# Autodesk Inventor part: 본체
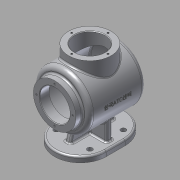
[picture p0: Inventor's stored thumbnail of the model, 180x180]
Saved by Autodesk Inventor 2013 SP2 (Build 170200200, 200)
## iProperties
Created: 2023-01
Part Number: 본체
Material: 알루미늄 6061
Document SubType Name: Modeling
Designer: aa
Density: 2.71 g/cm^3
Mass: 1038.32 g
Surface Area: 1157.53 cm^2
Volume: 383.145 cm^3
Author: aa
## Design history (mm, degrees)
sketch "스케치1"
  geometry: L1 (-63, 0)-(59, 0); L2 (-63, 0)-(-63, 38); L3 (-63, 38)-(-51, 38); L4 (-51, 38)-(-51, 50); L5 (-51, 50)-(48.087, 50); L6 (-63, 27)-(-46, 27); L7 (-46, 27)-(-46, 45); L8 (-46, 45)-(44.83, 45); A1 r 120 centre (-61, 0) between (59, 0) and (48.087, 50); A2 r 115 centre (-61, 0) between (54, 0) and (44.83, 45); 2 further points
  constraints: 16 end point, 4 parallel, 4 point on circle, 3 perpendicular, 3 point on line, 2 centre point, 1 coincident, 1 horizontal, 1 horizontal alignment, 1 midpoint
  dimensions: "d0" = 122 distance of L1.start L1.end; "d1" = 120 radius of A1; "d2" = 76 diameter of L3 L1; "d3" = 100 diameter of L5 L1; "d4" = 12 distance of L2.end L3.end; "d5" = 5 radial gap between concentric circles of A1 A2; "d6" = 54 diameter of L6 L1; "d7" = 90 diameter of L8 L1; "d8" = 17 distance of L6.start L6.end; "d57" = 59 distance of L1.end point (0, 0)
revolve "회전1" sketch "스케치1" stored, may be unused: angle "d9" = 90 deg
fillet "모깎기1" dims "d10" = 8
fillet "모깎기2" dims "d11" = 3
fillet "모깎기3" dims "d12" = 3
chamfer "모따기1" distance "d13" = 1; stored, may be unused: second distance "d14" = 2, angle "d15" = 45 deg
sketch "스케치2"
  geometry: C1 r 38 at (0, 0) reference; 1 further point
  constraints: 1 vertical alignment
  dimensions: "d16" = 32.5 distance of C1.centre point (0, 32.5)
hole "구멍1" sketch "스케치2" at (0, 32.5) diameter "d17" = 3.242; stored, may be unused: countersink angle "d21" = 90 deg, drill point angle "d23" = 118 deg; dims "d18" = 8, "d19" = 4, "d20" = 2, "d22" = 10
fillet "모깎기4" dims "d27" = 3
node "작업 평면1"
sketch "스케치3"
  geometry: L1 (51, 42)-(51, -42) reference; C1 r 38 at (0, 0); 1 further point
  constraints: 1 centre point, 1 coincident
  dimensions: "d29" = 76 diameter of C1; "d30" = 51 distance from line of C1.centre L1
extrude "돌출1" join sketch "스케치3" stored distance "d31" = 10; taper "d32" = 0 deg
sketch "스케치4"
  geometry: C1 r 38 at (0, 0) reference; C2 r 27 at (0, 0); 1 further point
  constraints: 1 centre point, 1 coincident
  dimensions: "d33" = 54 diameter of C2
extrude "돌출2" cut sketch "스케치4" stored distance "d34" = 10; taper "d35" = 0 deg
chamfer "모따기2" distance "d36" = 1; stored, may be unused: second distance "d37" = 2, angle "d38" = 45 deg
sketch "스케치5"
  geometry: C1 r 38 at (0, 0) reference; 2 further points
  constraints: 1 vertical alignment
  dimensions: "d39" = 32.5 distance of C1.centre point (0, 32.5)
hole "구멍2" sketch "스케치5" at (0, 32.5) diameter "d40" = 3.242; stored, may be unused: countersink angle "d44" = 90 deg, drill point angle "d46" = 118 deg; dims "d41" = 8, "d42" = 4, "d43" = 2, "d45" = 10
fillet "모깎기5" dims "d50" = 3
node "작업 평면2"
sketch "스케치6"
  geometry: L1 (63, 38)-(63, -38) reference; L2 (17, -46)-(-17, -46); L3 (17, 46)-(-17, 46); A1 r 46 centre (17, 0) between (17, -46) and (17, 46); A2 r 46 centre (-17, 0) between (-17, 46) and (-17, -46); 1 further point
  constraints: 5 tangent, 4 end point, 4 point on circle, 2 centre point, 2 horizontal alignment
  dimensions: "d52" = 92 diameter of A1; "d53" = 92 diameter of A2; "d54" = 126 dimension on A2 A1
extrude "돌출3" join sketch "스케치6" distance "d55" = 10; taper "d56" = 0 deg
sketch "스케치7"
  geometry: 2 further points
  dimensions: "d58" = 30 horizontal distance of point (0, 0) point (-30, 30); "d59" = 30 horizontal distance of point (0, 0) point (-30, 30)
hole "구멍3" sketch "스케치7" at (-30, 30) diameter "d60" = 9; stored, may be unused: countersink angle "d64" = 90 deg, drill point angle "d66" = 118 deg; dims "d61" = 8, "d62" = 4, "d63" = 2, "d65" = 10
fillet "모깎기6" dims "d73" = 3
sketch "스케치8"
  geometry: L1 (-5, -35)-(5, -35); L2 (5, -35)-(5, 35); L3 (5, 35)-(-5, 35); L4 (-5, 35)-(-5, -35); L5 (-5, -35)-(5, 35); L6 (5, -35)-(-5, 35); 1 further point
  constraints: 12 end point, 2 midpoint, 2 parallel, 1 horizontal, 1 perpendicular
  dimensions: "d74" = 10 distance of L3.end L2.end; "d75" = 70 distance of L2.end L1.end
extrude "돌출4" join sketch "스케치8" stored distance "d76" = 10; taper "d77" = 0 deg
sketch "스케치9"
  geometry: L1 (-62, 27)-(-63, 28) reference; L2 (-63, 28)-(-63, 30.879) reference; L3 (-63, 30.879)-(-53, 30.879) reference; L4 (-53, 30.879)-(-52.026, 32.5) reference; L5 (-52.026, 32.5)-(-53, 34.121) reference; L6 (-53, 34.121)-(-63, 34.121) reference; L7 (-63, 34.121)-(-63, 38) reference; L8 (-63, 38)-(-54, 38) reference; L9 (-51, 41)-(-51, 42) reference; L10 (-43, 50)-(-41, 50) reference; L11 (-38, 53)-(-38, 64) reference; L12 (-38, 64)-(-34.121, 64) reference; L13 (-34.121, 64)-(-34.121, 54) reference; L14 (-34.121, 54)-(-32.5, 53.026) reference; L15 (-32.5, 53.026)-(-30.879, 54) reference; L16 (-30.879, 54)-(-30.879, 64) reference; L17 (-30.879, 64)-(-28, 64) reference; L18 (-28, 64)-(-27, 63) reference; L19 (-27, 63)-(-27, 45) reference; L20 (-27, 45)-(-43, 45) reference; L21 (-46, 42)-(-46, 27) reference; L22 (-46, 27)-(-62, 27) reference; L23 (-60, -70)-(-5, -70) reference; L24 (-5, -70)-(-5, -50) reference; L25 (-5, -50)-(-43, -50) reference; L26 (-51, -42)-(-51, -41) reference; L27 (-54, -38)-(-63, -38) reference; L28 (-63, -38)-(-63, -34.121) reference; L29 (-63, -34.121)-(-53, -34.121) reference; L30 (-53, -34.121)-(-52.026, -32.5) reference; L31 (-52.026, -32.5)-(-53, -30.879) reference; L32 (-53, -30.879)-(-63, -30.879) reference; L33 (-63, -30.879)-(-63, -28) reference; L34 (-63, -28)-(-62, -27) reference; L35 (-62, -27)-(-46, -27) reference; L36 (-46, -27)-(-46, -42) reference; L37 (-43, -45)-(42.827, -45) reference; L38 (42.827, 45)-(27, 45) reference; L39 (27, 45)-(27, 63) reference; L40 (27, 63)-(28, 64) reference; L41 (28, 64)-(30.879, 64) reference; L42 (30.879, 64)-(30.879, 54) reference; L43 (30.879, 54)-(32.5, 53.026) reference; L44 (32.5, 53.026)-(34.121, 54) reference; L45 (34.121, 54)-(34.121, 64) reference; L46 (34.121, 64)-(38, 64) reference; L47 (38, 64)-(38, 53) reference; L48 (41, 50)-(42.827, 50) reference; L49 (42.827, -50)-(5, -50) reference; L50 (5, -50)-(5, -70) reference; L51 (5, -70)-(60, -70) reference; L52 (63, -73)-(63, -80) reference; L53 (63, -80)-(-63, -80) reference; L54 (-63, -80)-(-63, -73) reference; L55 (-40, -70)-(-34.641, -50); A1 r 3 centre (-54, 41) between (-54, 38) and (-51, 41) reference; A2 r 8 centre (-43, 42) between (-43, 50) and (-51, 42) reference; A3 r 3 centre (-43, 42) between (-43, 45) and (-46, 42) reference; A4 r 3 centre (-60, -73) between (-60, -70) and (-63, -73) reference; A5 r 8 centre (-43, -42) between (-51, -42) and (-43, -50) reference; A6 r 3 centre (-54, -41) between (-51, -41) and (-54, -38) reference; A7 r 3 centre (-43, -42) between (-46, -42) and (-43, -45) reference; A8 r 3 centre (42.827, -42) between (42.827, -45) and (45.608, -43.125) reference; A9 r 115 centre (-61, 0) between (45.608, -43.125) and (45.608, 43.125) reference; A10 r 3 centre (42.827, 42) between (45.608, 43.125) and (42.827, 45) reference; A11 r 8 centre (42.827, 42) between (50.243, 45) and (42.827, 50) reference; A12 r 120 centre (-61, 0) between (50.243, -45) and (50.243, 45) reference; A13 r 8 centre (42.827, -42) between (42.827, -50) and (50.243, -45) reference; A14 r 3 centre (60, -73) between (63, -73) and (60, -70) reference; 1 further point
  constraints: 2 end point, 2 point on line, 2 other
  dimensions: "d78" = 23 distance from line of L55.start L54; "d79" = 105 deg angle of L55 L23
feature "리브1" sketch "스케치9" dims "d80" = 1, "d81" = 10, "d82" = 0, "d83" = 0, "d84" = 1, "d85" = 1
fillet "모깎기7" dims "d86" = 3
fillet "모깎기8" dims "d87" = 3
node "작업 평면3"
sketch "스케치10"
  geometry: L1 (-63, -38)-(-63, 38) reference; L2 (63, -80)-(17, -80) reference; 2 further points
  constraints: 1 other
  dimensions: "d89" = 63 distance from line of point (0, 0) L1; "d90" = 80 distance from line of L2 point (0, 0)
feature "엠보싱1" sketch "스케치10" dims "d91" = 0.5, "d92" = 0
node "솔리드1"
pattern_circular "원형 패턴1" dims angle "d25" = 360 deg
pattern_circular "원형 패턴2" dims angle "d48" = 360 deg
pattern_linear "직사각형 패턴1" dims "d69" = 60
mirror "대칭1"
node "절단 모서리 투영1"
other parameters: "d28" = 64
